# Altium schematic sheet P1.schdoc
size 1117 x 863 mm; Symbol: Drawing-Symbol_A4; @Project Name: WYVERN-E; @Page Count: 1; @Update Date: 2026-08-05; @Create Date: 2026-08-05; @Schematic Name: Schematic1; @Page No: 1; @Page Name: P1; Company: EasyEDA.com; Version: V1.0; Page Size: A4; Device: Drawing-Symbol_A4; @Create Time: 14:42:15; @Update Time: 14:42:15; Border: 1; Width: 4400; Height: 3400; Region Start: 1; X Region Count: 6; Y Region Count: 4; Blade Width: 10; Title Block Position: 3; @Board Name: Board1
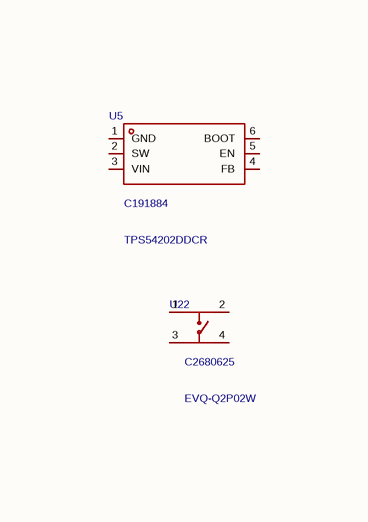
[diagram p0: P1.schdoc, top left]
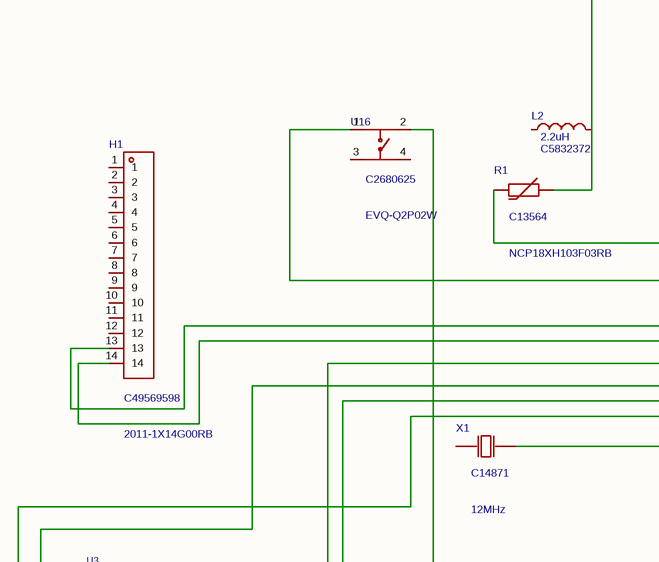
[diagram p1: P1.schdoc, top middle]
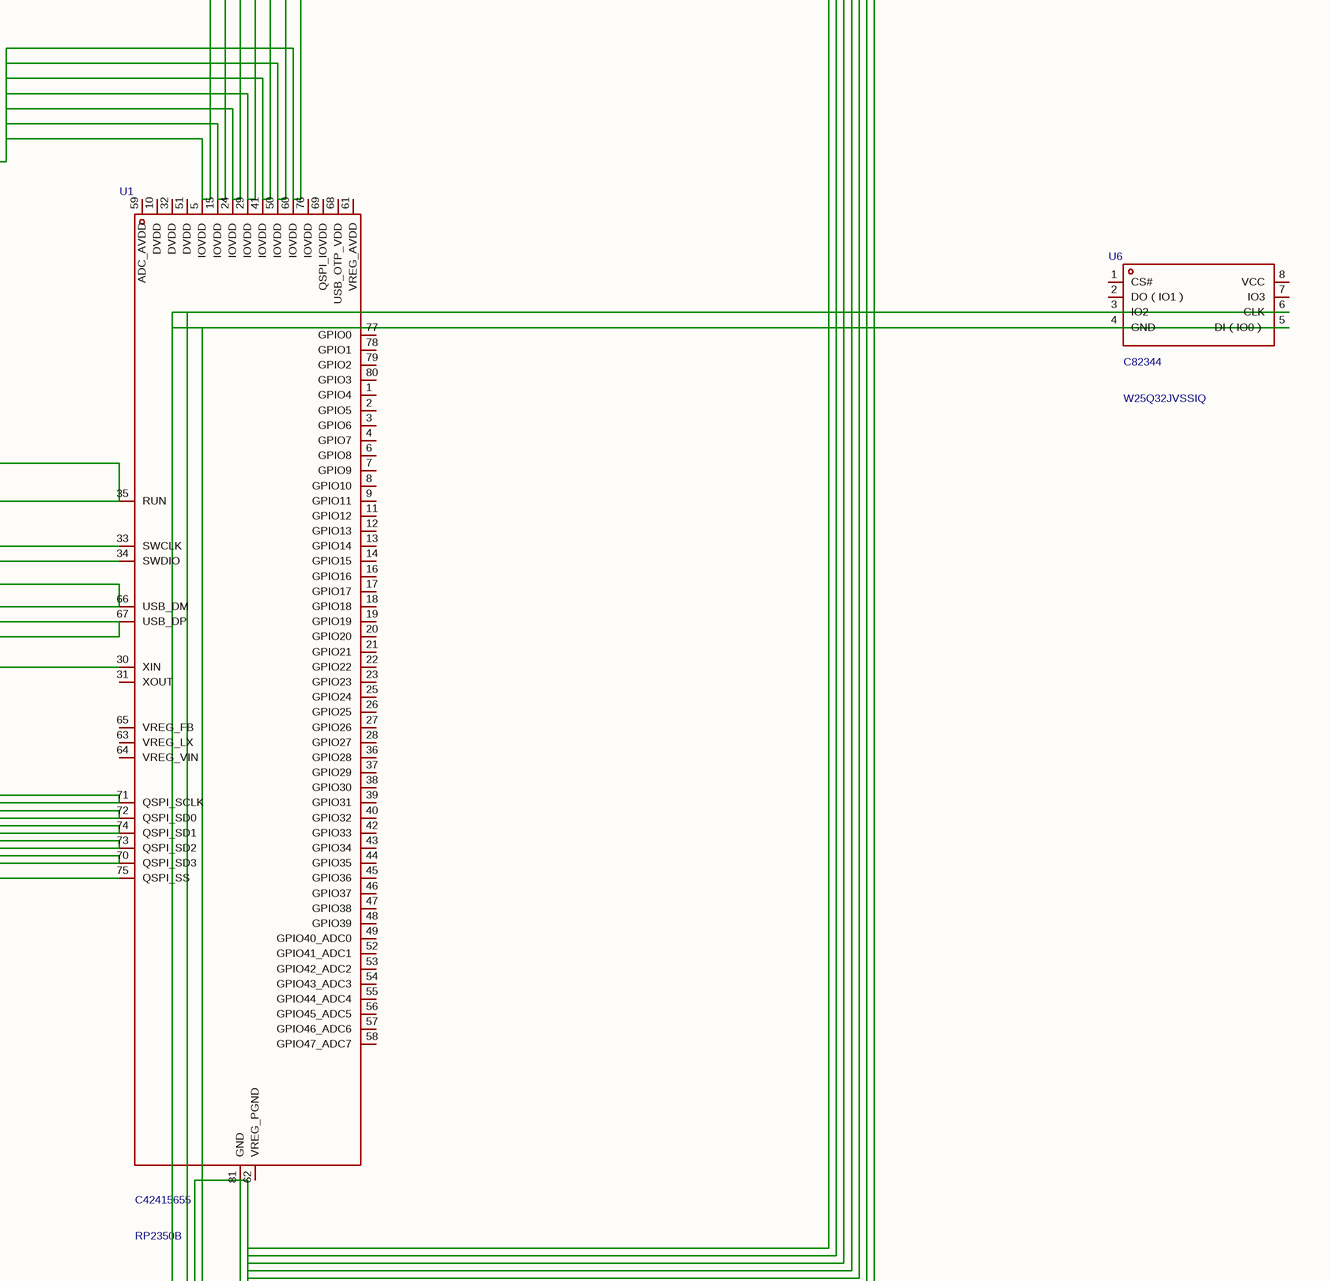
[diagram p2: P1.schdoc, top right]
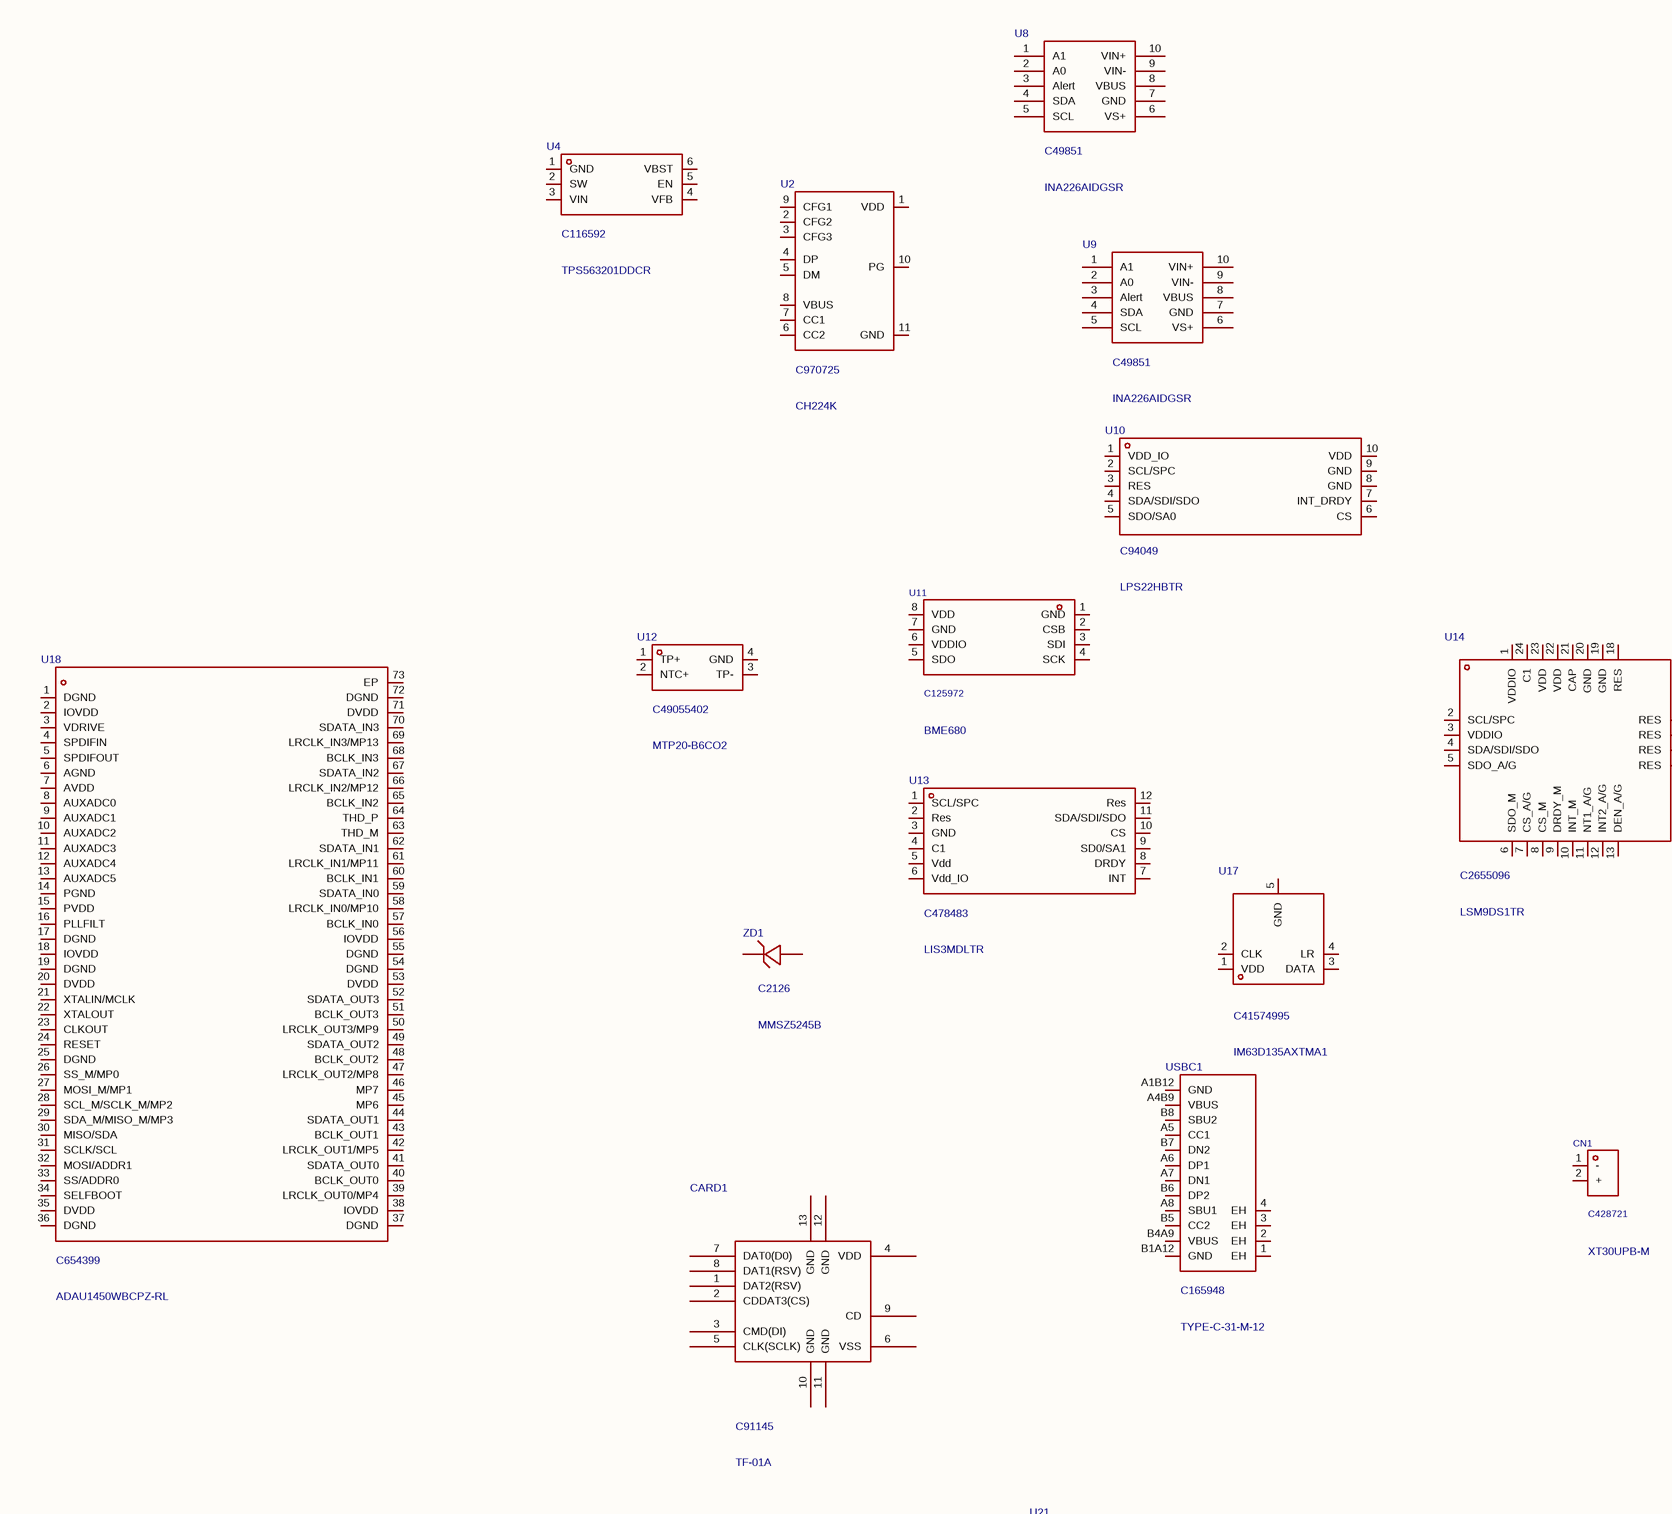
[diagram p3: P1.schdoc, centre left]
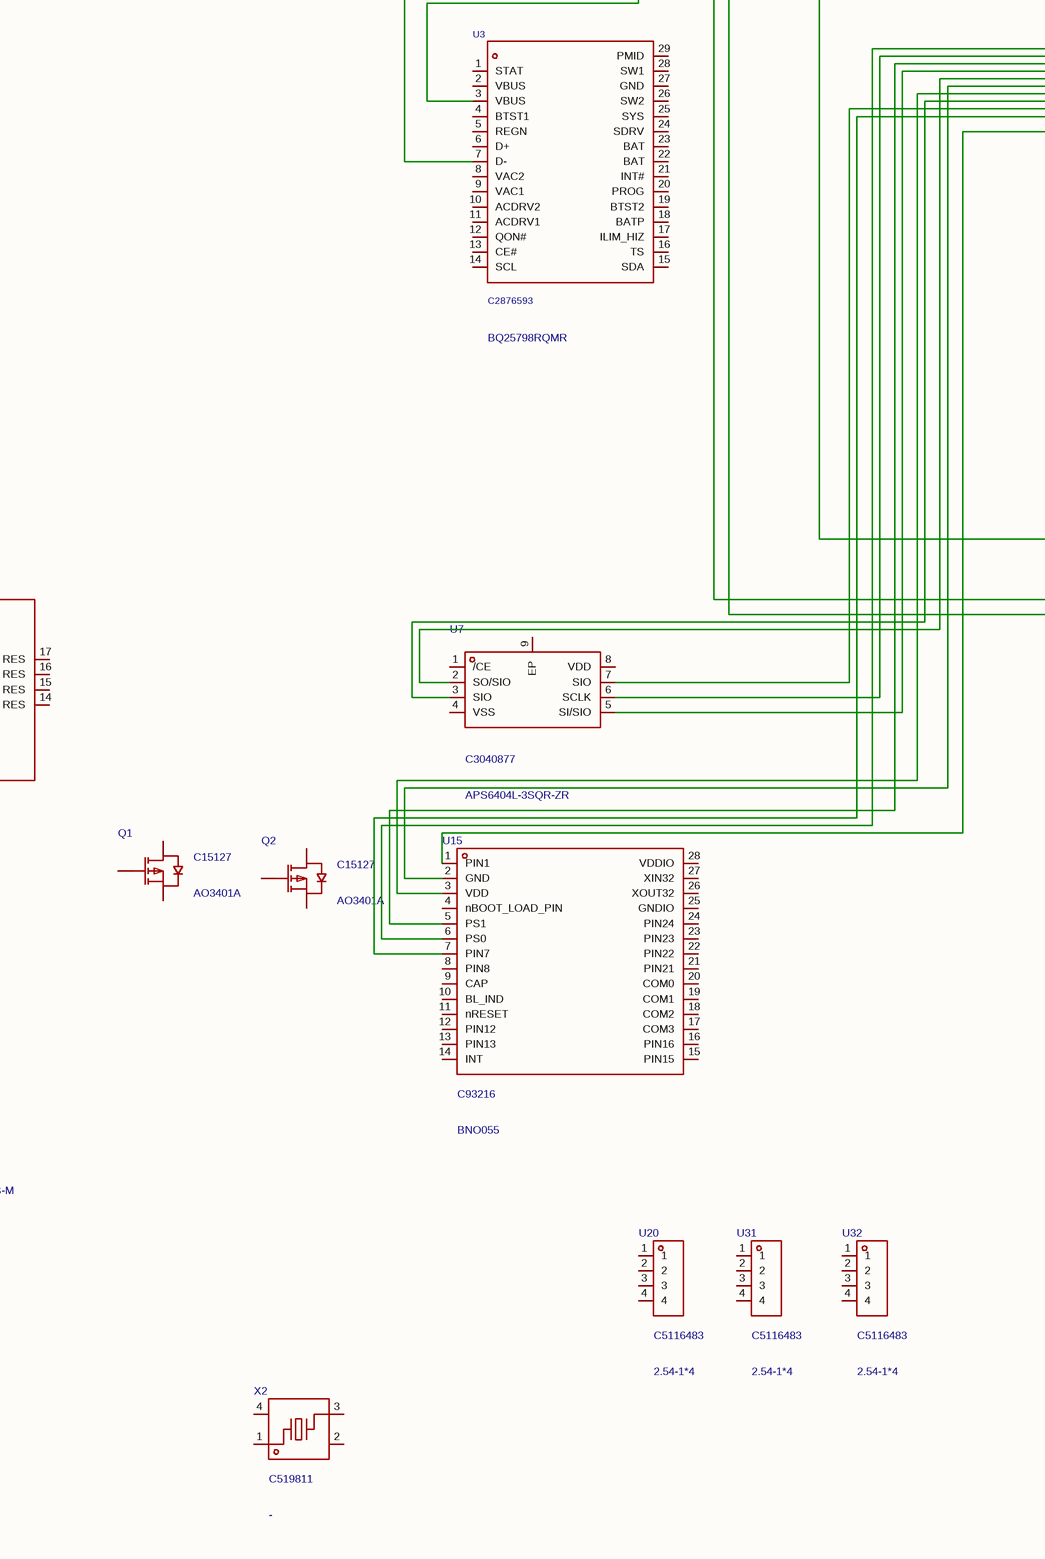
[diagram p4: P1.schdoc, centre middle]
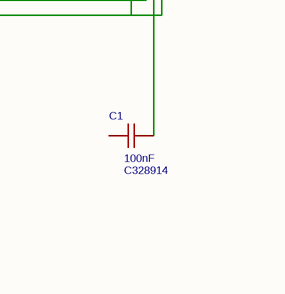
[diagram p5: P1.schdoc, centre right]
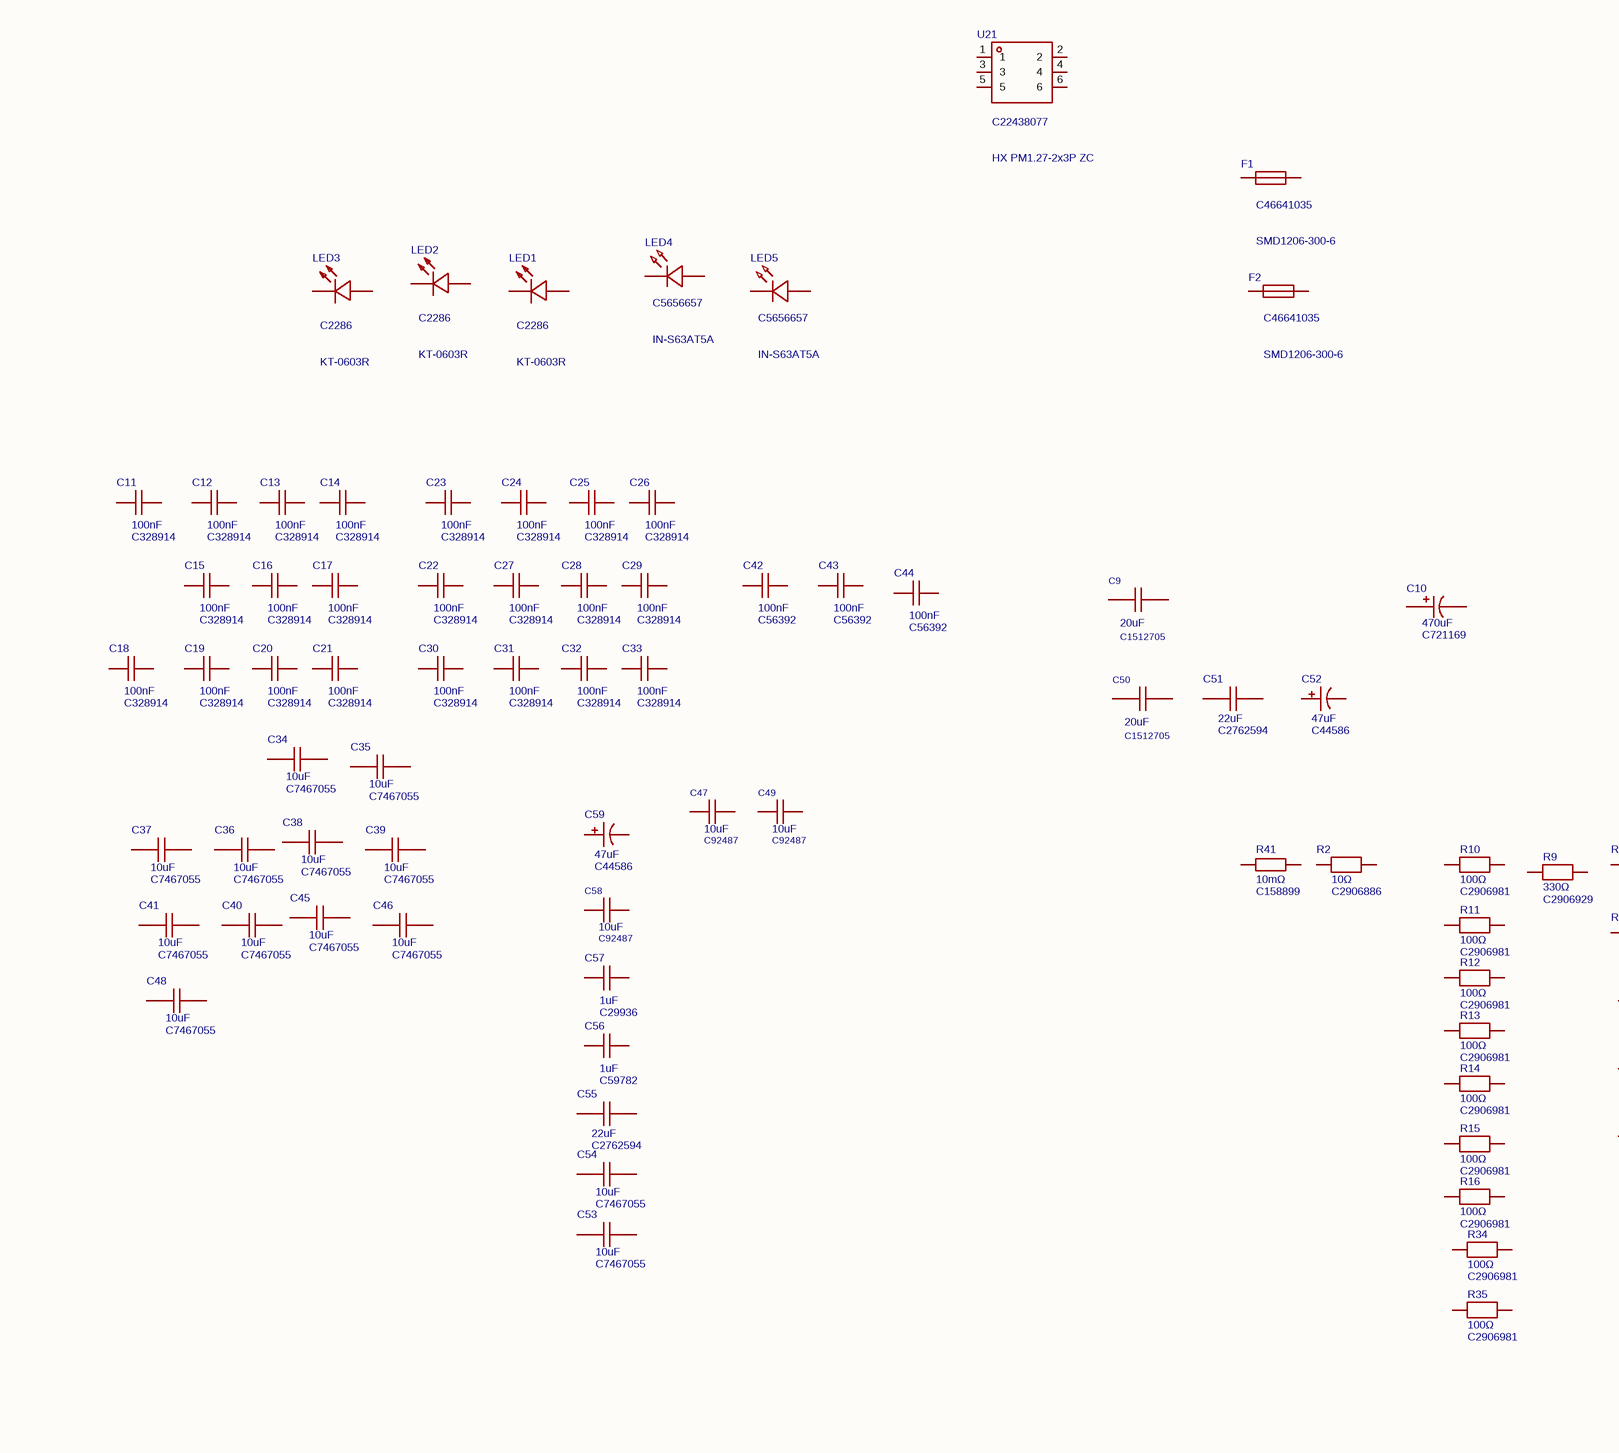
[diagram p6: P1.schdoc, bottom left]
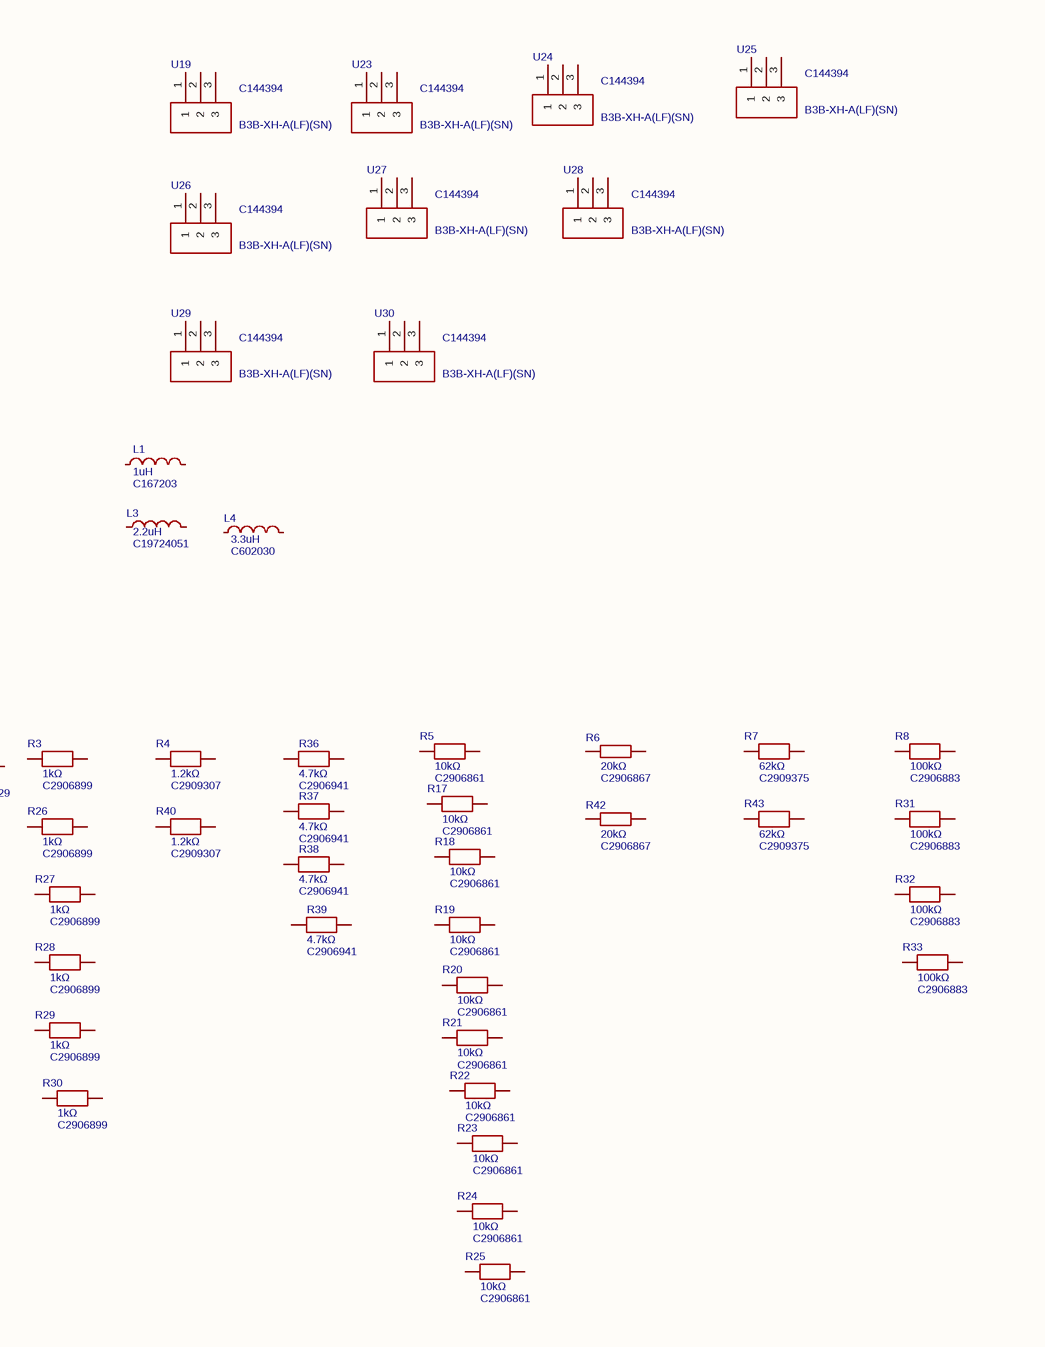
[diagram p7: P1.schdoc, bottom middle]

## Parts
C1  100nF  Supplier Part: C328914  [C0402]
C9  20uF  Supplier Part: C1512705  [C1812]
C10  470uF  Supplier Part: C721169  [CAP-TH_BD8.0-P3.50-D0.6-FD]
C11  100nF  Supplier Part: C328914  [C0402]
C12  100nF  Supplier Part: C328914  [C0402]
C13  100nF  Supplier Part: C328914  [C0402]
C14  100nF  Supplier Part: C328914  [C0402]
C15  100nF  Supplier Part: C328914  [C0402]
C16  100nF  Supplier Part: C328914  [C0402]
C17  100nF  Supplier Part: C328914  [C0402]
C18  100nF  Supplier Part: C328914  [C0402]
C19  100nF  Supplier Part: C328914  [C0402]
C20  100nF  Supplier Part: C328914  [C0402]
C21  100nF  Supplier Part: C328914  [C0402]
C22  100nF  Supplier Part: C328914  [C0402]
C23  100nF  Supplier Part: C328914  [C0402]
C24  100nF  Supplier Part: C328914  [C0402]
C25  100nF  Supplier Part: C328914  [C0402]
C26  100nF  Supplier Part: C328914  [C0402]
C27  100nF  Supplier Part: C328914  [C0402]
C28  100nF  Supplier Part: C328914  [C0402]
C29  100nF  Supplier Part: C328914  [C0402]
C30  100nF  Supplier Part: C328914  [C0402]
C31  100nF  Supplier Part: C328914  [C0402]
C32  100nF  Supplier Part: C328914  [C0402]
C33  100nF  Supplier Part: C328914  [C0402]
C34  10uF  Supplier Part: C7467055  [C0603]
C35  10uF  Supplier Part: C7467055  [C0603]
C36  10uF  Supplier Part: C7467055  [C0603]
C37  10uF  Supplier Part: C7467055  [C0603]
C38  10uF  Supplier Part: C7467055  [C0603]
C39  10uF  Supplier Part: C7467055  [C0603]
C40  10uF  Supplier Part: C7467055  [C0603]
C41  10uF  Supplier Part: C7467055  [C0603]
C42  100nF  Supplier Part: C56392  [C0402]
C43  100nF  Supplier Part: C56392  [C0402]
C44  100nF  Supplier Part: C56392  [C0402]
C45  10uF  Supplier Part: C7467055  [C0603]
C46  10uF  Supplier Part: C7467055  [C0603]
C47  10uF  Supplier Part: C92487  [C0603]
C48  10uF  Supplier Part: C7467055  [C0603]
C49  10uF  Supplier Part: C92487  [C0603]
C50  20uF  Supplier Part: C1512705  [C1812]
C51  22uF  Supplier Part: C2762594  [C0603]
C52  47uF  Supplier Part: C44586  [CAP-TH_BD5.0-P2.00-D0.8-FD]
C53  10uF  Supplier Part: C7467055  [C0603]
C54  10uF  Supplier Part: C7467055  [C0603]
C55  22uF  Supplier Part: C2762594  [C0603]
C56  1uF  Supplier Part: C59782  [C0603]
C57  1uF  Supplier Part: C29936  [C0603]
C58  10uF  Supplier Part: C92487  [C0603]
C59  47uF  Supplier Part: C44586  [CAP-TH_BD5.0-P2.00-D0.8-FD]
CARD1  TF-01A  Supplier Part: C91145  [TF-SMD_TF-01A]
CN1  XT30UPB-M  Supplier Part: C428721  [CONN-TH_XT30UPB-M]
F1  SMD1206-300-6  Supplier Part: C46641035  [F1206]
F2  SMD1206-300-6  Supplier Part: C46641035  [F1206]
H1  2011-1X14G00RB  Supplier Part: C49569598  [HDR-TH_14P-P2.54-H-M-W6.0-N]
L1  1uH  Supplier Part: C167203  [IND-SMD_L4.4-W4.2]
L2  2.2uH  Supplier Part: C5832372  [IND-SMD_L2.5-W2.0_MHCHL2520]
L3  2.2uH  Supplier Part: C19724051  [IND-SMD_L5.5-W5.2_NBMC0530N]
L4  3.3uH  Supplier Part: C602030  [IND-SMD_L4.0-W4.0]
LED1  KT-0603R  Supplier Part: C2286  [LED-SMD_L1.6-W0.8-R-RD]
LED2  KT-0603R  Supplier Part: C2286  [LED-SMD_L1.6-W0.8-R-RD]
LED3  KT-0603R  Supplier Part: C2286  [LED-SMD_L1.6-W0.8-R-RD]
LED4  IN-S63AT5A  Supplier Part: C5656657  [LED0603-RD]
LED5  IN-S63AT5A  Supplier Part: C5656657  [LED0603-RD]
Q1  AO3401A  Supplier Part: C15127  [SOT-23_L2.9-W1.3-P1.90-LS2.4-BR]
Q2  AO3401A  Supplier Part: C15127  [SOT-23_L2.9-W1.3-P1.90-LS2.4-BR]
R1  NCP18XH103F03RB  Supplier Part: C13564  [R0603]
R2  10Ω  Supplier Part: C2906886  [R0402]
R3  1kΩ  Supplier Part: C2906899  [R0402]
R4  1.2kΩ  Supplier Part: C2909307  [R0402]
R5  10kΩ  Supplier Part: C2906861  [R0402]
R6  20kΩ  Supplier Part: C2906867  [R0402]
R7  62kΩ  Supplier Part: C2909375  [R0402]
R8  100kΩ  Supplier Part: C2906883  [R0402]
R9  330Ω  Supplier Part: C2906929  [R0402]
R10  100Ω  Supplier Part: C2906981  [R0603]
R11  100Ω  Supplier Part: C2906981  [R0603]
R12  100Ω  Supplier Part: C2906981  [R0603]
R13  100Ω  Supplier Part: C2906981  [R0603]
R14  100Ω  Supplier Part: C2906981  [R0603]
R15  100Ω  Supplier Part: C2906981  [R0603]
R16  100Ω  Supplier Part: C2906981  [R0603]
R17  10kΩ  Supplier Part: C2906861  [R0402]
R18  10kΩ  Supplier Part: C2906861  [R0402]
R19  10kΩ  Supplier Part: C2906861  [R0402]
R20  10kΩ  Supplier Part: C2906861  [R0402]
R21  10kΩ  Supplier Part: C2906861  [R0402]
R22  10kΩ  Supplier Part: C2906861  [R0402]
R23  10kΩ  Supplier Part: C2906861  [R0402]
R24  10kΩ  Supplier Part: C2906861  [R0402]
R25  10kΩ  Supplier Part: C2906861  [R0402]
R26  1kΩ  Supplier Part: C2906899  [R0402]
R27  1kΩ  Supplier Part: C2906899  [R0402]
R28  1kΩ  Supplier Part: C2906899  [R0402]
R29  1kΩ  Supplier Part: C2906899  [R0402]
R30  1kΩ  Supplier Part: C2906899  [R0402]
R31  100kΩ  Supplier Part: C2906883  [R0402]
R32  100kΩ  Supplier Part: C2906883  [R0402]
R33  100kΩ  Supplier Part: C2906883  [R0402]
R34  100Ω  Supplier Part: C2906981  [R0603]
R35  100Ω  Supplier Part: C2906981  [R0603]
R36  4.7kΩ  Supplier Part: C2906941  [R0402]
R37  4.7kΩ  Supplier Part: C2906941  [R0402]
R38  4.7kΩ  Supplier Part: C2906941  [R0402]
R39  4.7kΩ  Supplier Part: C2906941  [R0402]
R40  1.2kΩ  Supplier Part: C2909307  [R0402]
R41  10mΩ  Supplier Part: C158899  [R0603]
R42  20kΩ  Supplier Part: C2906867  [R0402]
R43  62kΩ  Supplier Part: C2909375  [R0402]
U1  RP2350B  Supplier Part: C42415655  [QFN-80_L10.0-W10.0-P0.40-TL-EP3.4]
U2  CH224K  Supplier Part: C970725  [ESSOP-10_L4.9-W3.9-P1.0-LS6.0-TL-EP]
U3  BQ25798RQMR  Supplier Part: C2876593  [QFN-29_L4.0-W4.0-P0.40-TL-BQ25792RQMR]
U4  TPS563201DDCR  Supplier Part: C116592  [SOT-23-6_L2.9-W1.6-P0.95-LS2.8-BR]
U5  TPS54202DDCR  Supplier Part: C191884  [SOT-23-6_L2.9-W1.6-P0.95-LS2.8-BL]
U6  W25Q32JVSSIQ  Supplier Part: C82344  [SOIC-8_L5.3-W5.3-P1.27-LS8.0-BL]
U7  APS6404L-3SQR-ZR  Supplier Part: C3040877  [USON-8_L3.0-W2.0-P0.50-BL-EP]
U8  INA226AIDGSR  Supplier Part: C49851  [MSOP-10_L3.0-W3.0-P0.50-LS5.0-BL]
U9  INA226AIDGSR  Supplier Part: C49851  [MSOP-10_L3.0-W3.0-P0.50-LS5.0-BL]
U10  LPS22HBTR  Supplier Part: C94049  [HLGA-10L_LPS22HBTR]
U11  BME680  Supplier Part: C125972  [LGA-8_L3.0-W3.0-P0.80-TR]
U12  MTP20-B6CO2  Supplier Part: C49055402  [TO-46-4_BD5.5-P1.80_MTP20-B6CO2]
U13  LIS3MDLTR  Supplier Part: C478483  [LGA-12_L2.0-W2.0-P0.50-BL]
U14  LSM9DS1TR  Supplier Part: C2655096  [LGA-24_L3.5-W3.0-P0.43-TL]
U15  BNO055  Supplier Part: C93216  [LGA-28_L5.2-W3.8-P0.50-BL]
U16  EVQ-Q2P02W  Supplier Part: C2680625  [SW-SMD_4P-L6.5-W6.0-P4.00-LS6.6-TL]
U17  IM63D135AXTMA1  Supplier Part: C41574995  [MIC-SMD_5P-L3.5-W2.7_IM66D130AXTMA1]
U18  ADAU1450WBCPZ-RL  Supplier Part: C654399  [LFCSP-72_L10.0-W9.8-P0.50-LS10.2-TL-EP5.5]
U19  B3B-XH-A(LF)(SN)  Supplier Part: C144394  [CONN-TH_3P-P2.50_A2501WV2-3P]
U20  2.54-1*4  Supplier Part: C5116483  [HDR-TH_4P-P2.54-V-M-1]
U21  HX PM1.27-2x3P ZC  Supplier Part: C22438077  [HDR-TH_6P-HX-PM1.27-2X3P-ZC]
U22  EVQ-Q2P02W  Supplier Part: C2680625  [SW-SMD_4P-L6.5-W6.0-P4.00-LS6.6-TL]
U23  B3B-XH-A(LF)(SN)  Supplier Part: C144394  [CONN-TH_3P-P2.50_A2501WV2-3P]
U24  B3B-XH-A(LF)(SN)  Supplier Part: C144394  [CONN-TH_3P-P2.50_A2501WV2-3P]
U25  B3B-XH-A(LF)(SN)  Supplier Part: C144394  [CONN-TH_3P-P2.50_A2501WV2-3P]
U26  B3B-XH-A(LF)(SN)  Supplier Part: C144394  [CONN-TH_3P-P2.50_A2501WV2-3P]
U27  B3B-XH-A(LF)(SN)  Supplier Part: C144394  [CONN-TH_3P-P2.50_A2501WV2-3P]
U28  B3B-XH-A(LF)(SN)  Supplier Part: C144394  [CONN-TH_3P-P2.50_A2501WV2-3P]
U29  B3B-XH-A(LF)(SN)  Supplier Part: C144394  [CONN-TH_3P-P2.50_A2501WV2-3P]
U30  B3B-XH-A(LF)(SN)  Supplier Part: C144394  [CONN-TH_3P-P2.50_A2501WV2-3P]
U31  2.54-1*4  Supplier Part: C5116483  [HDR-TH_4P-P2.54-V-M-1]
U32  2.54-1*4  Supplier Part: C5116483  [HDR-TH_4P-P2.54-V-M-1]
USBC1  TYPE-C-31-M-12  Supplier Part: C165948  [USB-C_SMD-TYPE-C-31-M-12_1]
X1  12MHz  Supplier Part: C14871  [HC-49S_L11.4-W4.8]
X2  -  Supplier Part: C519811  [CRYSTAL-SMD_4P-L3.2-W2.5-BL]
ZD1  MMSZ5245B  Supplier Part: C2126  [SOD-123_L2.8-W1.8-LS3.7-RD]

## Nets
NetC1_2: C1.2 U1.81(GND) U16.2
NetH1_13: H1.13 U1.33(SWCLK)
NetH1_14: H1.14 U1.34(SWDIO)
NetL2_2: L2.2 R1.2 U1.5(IOVDD) U1.15(IOVDD) U1.24(IOVDD) U1.29(IOVDD) U1.41(IOVDD) U1.50(IOVDD) U1.60(IOVDD)
NetR1_1: R1.1 U1.35(RUN) U16.1
NetU1_30: U1.30(XIN) X1.1(OSC1)
NetU1_66: U1.66(USB_DM) U1.67(USB_DP) U3.3(VBUS) U3.7(D-) U6.3(IO2) U6.4(GND) U6.5(DI（IO0）) U6.6(CLK)
NetU1_70: U1.70(QSPI_SD3) U7.7(SIO) U15.7(PIN7)
NetU1_71: U1.71(QSPI_SCLK) U7.6(SCLK) U15.6(PS0)
NetU1_72: U1.72(QSPI_SD0) U7.5(SI/SIO) U15.5(PS1)
NetU1_73: U1.73(QSPI_SD2) U7.3(SIO) U15.3(VDD)
NetU1_74: U1.74(QSPI_SD1) U7.2(SO/SIO) U15.2(GND)
NetU1_75: U1.75(QSPI_SS) U15.1(PIN1)

Not connected (* = marked no-connect by the designer): C1 1; C9 1 2; C10 1 2; C11 1 2; C12 1 2; C13 1 2; C14 1 2; C15 1 2; C16 1 2; C17 1 2; C18 1 2; C19 1 2; C20 1 2; C21 1 2; C22 1 2; C23 1 2; C24 1 2; C25 1 2; C26 1 2; C27 1 2; C28 1 2; C29 1 2; C30 1 2; C31 1 2; C32 1 2; C33 1 2; C34 1 2; C35 1 2; C36 1 2; C37 1 2; C38 1 2; C39 1 2; C40 1 2; C41 1 2; C42 1 2; C43 1 2; C44 1 2; C45 1 2; C46 1 2; C47 1 2; C48 1 2; C49 1 2; C50 1 2; C51 1 2; C52 1 2; C53 1 2; C54 1 2; C55 1 2; C56 1 2; C57 1 2; C58 1 2; C59 1 2; CARD1 1(DAT2(RSV)) 2(CDDAT3(CS)) 3(CMD(DI)) 4(VDD) 5(CLK(SCLK)) 6(VSS) 7(DAT0(D0)) 8(DAT1(RSV)) 9(CD) 10(GND) 11(GND) 12(GND) 13(GND); CN1 1(-) 2(+); F1 1 2; F2 1 2; H1 1 2 3 4 5 6 7 8 9 10 11 12; L1 1 2; L2 1; L3 1 2; L4 1 2; LED1 1(A) 2(K); LED2 1(A) 2(K); LED3 1(A) 2(K); LED4 1(C) 2(A); LED5 1(C) 2(A); Q1 1(G) 2(S) 3(D); Q2 1(G) 2(S) 3(D); R2 1 2; R3 1 2; R4 1 2; R5 1 2; R6 1 2; R7 1 2; R8 1 2; R9 1 2; R10 1 2; R11 1 2; R12 1 2; R13 1 2; R14 1 2; R15 1 2; R16 1 2; R17 1 2; R18 1 2; R19 1 2; R20 1 2; R21 1 2; R22 1 2; R23 1 2; R24 1 2; R25 1 2; R26 1 2; R27 1 2; R28 1 2; R29 1 2; R30 1 2; R31 1 2; R32 1 2; R33 1 2; R34 1 2; R35 1 2; R36 1 2; R37 1 2; R38 1 2; R39 1 2; R40 1 2; R41 1 2; R42 1 2; R43 1 2; U1 1(GPIO4) 2(GPIO5) 3(GPIO6) 4(GPIO7) 6(GPIO8) 7(GPIO9) 8(GPIO10) 9(GPIO11) 10(DVDD) 11(GPIO12) 12(GPIO13) 13(GPIO14) 14(GPIO15) 16(GPIO16) 17(GPIO17) 18(GPIO18) 19(GPIO19) 20(GPIO20) 21(GPIO21) 22(GPIO22) 23(GPIO23) 25(GPIO24) 26(GPIO25) 27(GPIO26) 28(GPIO27) 31(XOUT) 32(DVDD) 36(GPIO28) 37(GPIO29) 38(GPIO30) 39(GPIO31) 40(GPIO32) 42(GPIO33) 43(GPIO34) 44(GPIO35) 45(GPIO36) 46(GPIO37) 47(GPIO38) 48(GPIO39) 49(GPIO40_ADC0) 51(DVDD) 52(GPIO41_ADC1) 53(GPIO42_ADC2) 54(GPIO43_ADC3) 55(GPIO44_ADC4) 56(GPIO45_ADC5) 57(GPIO46_ADC6) 58(GPIO47_ADC7) 59(ADC_AVDD) 61(VREG_AVDD) 62(VREG_PGND) 63(VREG_LX) 64(VREG_VIN) 65(VREG_FB) 68(USB_OTP_VDD) 69(QSPI_IOVDD) 76(IOVDD) 77(GPIO0) 78(GPIO1) 79(GPIO2) 80(GPIO3); U2 1(VDD) 2(CFG2) 3(CFG3) 4(DP) 5(DM) 6(CC2) 7(CC1) 8(VBUS) 9(CFG1) 10(PG) 11(GND); U3 1(STAT) 2(VBUS) 4(BTST1) 5(REGN) 6(D+) 8(VAC2) 9(VAC1) 10(ACDRV2) 11(ACDRV1) 12(QON#) 13(CE#) 14(SCL) 15(SDA) 16(TS) 17(ILIM_HIZ) 18(BATP) 19(BTST2) 20(PROG) 21(INT#) 22(BAT) 23(BAT) 24(SDRV) 25(SYS) 26(SW2) 27(GND) 28(SW1) 29(PMID); U4 1(GND) 2(SW) 3(VIN) 4(VFB) 5(EN) 6(VBST); U5 1(GND) 2(SW) 3(VIN) 4(FB) 5(EN) 6(BOOT); U6 1(CS#) 2(DO（IO1）) 7(IO3) 8(VCC); U7 1(/CE) 4(VSS) 8(VDD) 9(EP); U8 1(A1) 2(A0) 3(Alert) 4(SDA) 5(SCL) 6(VS+) 7(GND) 8(VBUS) 9(VIN-) 10(VIN+); U9 1(A1) 2(A0) 3(Alert) 4(SDA) 5(SCL) 6(VS+) 7(GND) 8(VBUS) 9(VIN-) 10(VIN+); U10 1(VDD_IO) 2(SCL/SPC) 3(RES) 4(SDA/SDI/SDO) 5(SDO/SA0) 6(CS) 7(INT_DRDY) 8(GND) 9(GND) 10(VDD); U11 1(GND) 2(CSB) 3(SDI) 4(SCK) 5(SDO) 6(VDDIO) 7(GND) 8(VDD); U12 1(TP+) 2(NTC+) 3(TP-) 4(GND); U13 1(SCL/SPC) 2(Res) 3(GND) 4(C1) 5(Vdd) 6(Vdd_IO) 7(INT) 8(DRDY) 9(SD0/SA1) 10(CS) 11(SDA/SDI/SDO) 12(Res); U14 1(VDDIO) 2(SCL/SPC) 3(VDDIO) 4(SDA/SDI/SDO) 5(SDO_A/G) 6(SDO_M) 7(CS_A/G) 8(CS_M) 9(DRDY_M) 10(INT_M) 11(NT1_A/G) 12(INT2_A/G) 13(DEN_A/G) 14(RES) 15(RES) 16(RES) 17(RES) 18(RES) 19(GND) 20(GND) 21(CAP) 22(VDD) 23(VDD) 24(C1); U15 4(nBOOT_LOAD_PIN) 8(PIN8) 9(CAP) 10(BL_IND) 11(nRESET) 12(PIN12) 13(PIN13) 14(INT) 15(PIN15) 16(PIN16) 17(COM3) 18(COM2) 19(COM1) 20(COM0) 21(PIN21) 22(PIN22) 23(PIN23) 24(PIN24) 25(GNDIO) 26(XOUT32) 27(XIN32) 28(VDDIO); U16 3 4; U17 1(VDD) 2(CLK) 3(DATA) 4(LR) 5(GND); U18 1(DGND) 2(IOVDD) 3(VDRIVE) 4(SPDIFIN) 5(SPDIFOUT) 6(AGND) 7(AVDD) 8(AUXADC0) 9(AUXADC1) 10(AUXADC2) 11(AUXADC3) 12(AUXADC4) 13(AUXADC5) 14(PGND) 15(PVDD) 16(PLLFILT) 17(DGND) 18(IOVDD) 19(DGND) 20(DVDD) 21(XTALIN/MCLK) 22(XTALOUT) 23(CLKOUT) 24(RESET) 25(DGND) 26(SS_M/MP0) 27(MOSI_M/MP1) 28(SCL_M/SCLK_M/MP2) 29(SDA_M/MISO_M/MP3) 30(MISO/SDA) 31(SCLK/SCL) 32(MOSI/ADDR1) 33(SS/ADDR0) 34(SELFBOOT) 35(DVDD) 36(DGND) 37(DGND) 38(IOVDD) 39(LRCLK_OUT0/MP4) 40(BCLK_OUT0) 41(SDATA_OUT0) 42(LRCLK_OUT1/MP5) 43(BCLK_OUT1) 44(SDATA_OUT1) 45(MP6) 46(MP7) 47(LRCLK_OUT2/MP8) 48(BCLK_OUT2) 49(SDATA_OUT2) 50(LRCLK_OUT3/MP9) 51(BCLK_OUT3) 52(SDATA_OUT3) 53(DVDD) 54(DGND) 55(DGND) 56(IOVDD) 57(BCLK_IN0) 58(LRCLK_IN0/MP10) 59(SDATA_IN0) 60(BCLK_IN1) 61(LRCLK_IN1/MP11) 62(SDATA_IN1) 63(THD_M) 64(THD_P) 65(BCLK_IN2) 66(LRCLK_IN2/MP12) 67(SDATA_IN2) 68(BCLK_IN3) 69(LRCLK_IN3/MP13) 70(SDATA_IN3) 71(DVDD) 72(DGND) 73(EP); U19 1 2 3; U20 1 2 3 4; U21 1 2 3 4 5 6; U22 1 2 3 4; U23 1 2 3; U24 1 2 3; U25 1 2 3; U26 1 2 3; U27 1 2 3; U28 1 2 3; U29 1 2 3; U30 1 2 3; U31 1 2 3 4; U32 1 2 3 4; USBC1 1(EH) 2(EH) 3(EH) 4(EH) A1B12(GND) A4B9(VBUS) A5(CC1) A6(DP1) A7(DN1) A8(SBU1) B1A12(GND) B4A9(VBUS) B5(CC2) B6(DP2) B7(DN2) B8(SBU2); X1 2(OSC2); X2 1 2(GND) 3 4(GND); ZD1 1(K) 2(A)

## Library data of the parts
C1 C11-C33 = FN15X104K160PNG: Capacitance:100nF Tolerance:±10% Tolerance:±10% Voltage Rating:16V Temperature Coefficient:X7R; Manufacturer: PSA(信昌电陶); AddInBom: yes; ModelId: b7d13df3e9464d7a99d0651d1a5b4d570819f05c4eef4c71ace90d822a990e87; ModelName: C0402_L1.0-W0.5-H0.5; ModelTransform: 39.37,19.685,0,0,0,0,0,0,0; Tolerance: ±10%; Voltage Rating: 16V; Temperature Coefficient: X7R
C9 C50 = C1812C206K3RLCAUTO: Capacitance:20uF Tolerance:±10% Tolerance:±10% Voltage Rated: Temperature Coefficient:; Manufacturer: KEMET(基美); AddInBom: yes; ModelId: 9490267e11c744c49bc8222b92720aba0819f05c4eef4c71ace90d822a990e87; ModelName: C1812_L4.5-W3.2-H2.6; ModelTransform: 177.165,125.984,0,0,0,0,0.0005,0,0; Tolerance: ±10%
C10 = ERF1EM471F12OT: Capacitance:470uF Tolerance:±20% Tolerance:±20% Voltage Rating:25V Ripple Current:- Equivalent Series Resistance(ESR):- Pin Spacing:3.5mm Diameter:8mm Height - Seated (Max):12mm Lifetime:- Operating Temperature:-40℃~+105℃ Operating Temperature:-40℃~+105℃; Manufacturer: AISHI(艾华集团); AddInBom: yes; ModelId: 26f37486632942dc87f6308ee91e8f400819f05c4eef4c71ace90d822a990e87; ModelName: CAP-TH_D8.0-H8.0-P3.50; ModelTransform: 314.96,314.862,0,180,0,0,0,0,-137.795; Tolerance: ±20%; Voltage Rating: 25V; Pin Spacing: 3.5mm
C34-C41 C45 C46 C48 C53 C54 = FCC0603X106M250CT: Capacitance:10uF Tolerance:±20% Tolerance:±20% Voltage Rating:25V Temperature Coefficient:X5R; Manufacturer: FOJAN(富捷); AddInBom: yes; ModelId: 624118aa3cc7497086c383c2d72e08520819f05c4eef4c71ace90d822a990e87; ModelName: C0603_L1.6-W0.8-H0.8; ModelTransform: 62.992,31.496,0,0,0,0,0,0,0; Tolerance: ±20%; Voltage Rating: 25V; Temperature Coefficient: X5R
C42-C44 = 0402B104K250NT: Capacitance:100nF Tolerance:±10% Tolerance:±10% Voltage Rating:25V Temperature Coefficient:X7R; Manufacturer: FH(风华); AddInBom: yes; ModelId: b7d13df3e9464d7a99d0651d1a5b4d570819f05c4eef4c71ace90d822a990e87; ModelName: C0402_L1.0-W0.5-H0.5; ModelTransform: 39.37,19.685,0,0,0,0,0,0,0; Tolerance: ±10%; Voltage Rating: 25V; Temperature Coefficient: X7R
C47 C49 C58 = CL10A106MO8NQNC: Capacitance:10uF Tolerance:±20% Tolerance:±20% Voltage Rating:16V Temperature Coefficient:X5R; Manufacturer: SAMSUNG(三星); AddInBom: yes; ModelId: 624118aa3cc7497086c383c2d72e08520819f05c4eef4c71ace90d822a990e87; ModelName: C0603_L1.6-W0.8-H0.8; ModelTransform: 62.992,31.496,0,0,0,0,0,0,0; Tolerance: ±20%; Voltage Rating: 16V; Temperature Coefficient: X5R
C51 C55 = CL10A226MO7JZNC: Capacitance:22uF Tolerance:±20% Tolerance:±20% Voltage Rating:16V Temperature Coefficient:X5R; Manufacturer: SAMSUNG(三星); AddInBom: yes; ModelId: 624118aa3cc7497086c383c2d72e08520819f05c4eef4c71ace90d822a990e87; ModelName: C0603_L1.6-W0.8-H0.8; ModelTransform: 62.992,31.496,0,0,0,0,0,0,0; Tolerance: ±20%; Voltage Rating: 16V; Temperature Coefficient: X5R
C52 C59 = KS476M025D07RR0VH2FP0: Capacitance:47uF Tolerance:±20% Tolerance:±20% Voltage Rating:25V Pin Spacing:2mm Diameter:5mm Height - Seated (Max):7mm Lifetime:1000hrs@105℃ Operating Temperature:-40℃~+105℃ Operating Temperature:-40℃~+105℃; Manufacturer: Chengx(承兴); Symbol: 47uF 25V 5*7; AddInBom: yes; ModelId: a6753ac7f17a4fce96dd233a0f76b1540819f05c4eef4c71ace90d822a990e87; ModelName: CAP-TH_D5.0×H7.0×P2.0; ModelTransform: 197.091,196.7911,0,0,0,0,0,0,-137.795; Tolerance: ±20%; Voltage Rating: 25V; Pin Spacing: 2mm
C56 = CL10B105KO8NNNC: Capacitance:1uF Tolerance:±10% Tolerance:±10% Voltage Rating:16V Temperature Coefficient:X7R; Manufacturer: SAMSUNG(三星); AddInBom: yes; ModelId: 624118aa3cc7497086c383c2d72e08520819f05c4eef4c71ace90d822a990e87; ModelName: C0603_L1.6-W0.8-H0.8; ModelTransform: 62.992,31.496,0,0,0,0,0,0,0; Tolerance: ±10%; Voltage Rating: 16V; Temperature Coefficient: X7R
C57 = CL10B105KA8NNNC: Capacitance:1uF Tolerance:±10% Tolerance:±10% Voltage Rating:25V Temperature Coefficient:X7R; Manufacturer: SAMSUNG(三星); AddInBom: yes; ModelId: 624118aa3cc7497086c383c2d72e08520819f05c4eef4c71ace90d822a990e87; ModelName: C0603_L1.6-W0.8-H0.8; ModelTransform: 62.992,31.496,0,0,0,0,0,0,0; Tolerance: ±10%; Voltage Rating: 25V; Temperature Coefficient: X7R
CARD1 = TF-01A_C91145: Card Connection Mode:Push-Push Card Type:MicroSD Card (TF Card) Connector Type:Connector and Ejector Additional Card Detection Pins:- Supplementary Features:With Locating Pins Height Above Board:1.85mm Operating Temperature:- Operating Temperature:-; Manufacturer: 韩国韩荣; Add into BOM: yes; ModelId: 5685a23adc9a4e3e9b914abe5ae03aae0819f05c4eef4c71ace90d822a990e87; ModelTransform: 633.85696,590.65303,0,0,0,0,0,-85.63,-23.622
CN1 = XT30UPB-M: Rated current:15A Rated voltage: colour:Yellow Connector type:Model aircraft plug contact resistance: interface form:Male insulating material: metal material:Gold plating; Manufacturer: AMASS(艾迈斯); Add into BOM: yes; ModelId: 8606296c6a2a4a0aa30f28b26a2c1e3a0819f05c4eef4c71ace90d822a990e87; ModelTransform: 401.574,204.724,0,0,0,0,0,0,-78.74; Rated current: 15A; interface form: Male
F1 F2 = SMD1206-300-6: Voltage - Max:6V Current - Max:40A Hold Current:3A Trip Current:6A Power Dissipation:1W Resistance - Initial (Ri) (Min):10mΩ Resistance - Post Trip (R1) (Max):50mΩ Time to Trip(Max):4s Operating Temperature:-40℃~+85℃ Operating Temperature:-40℃~+85℃ Length; Manufacturer: R+O(宏嘉诚); Add into BOM: yes; ModelId: 61372169742747e19cbd4ac5ee5e48b10819f05c4eef4c71ace90d822a990e87; ModelName: F1206_L3.2-W1.7-H0.6; ModelTransform: 125.984,66.929,0,0,0,0,0,0,0; Voltage - Max: 6V; Current - Max: 40A; Hold Current: 3A; Trip Current: 6A; Power Dissipation: 1W; Resistance - Initial (Ri) (Min): 10mΩ; Resistance - Post Trip (R1) (Max): 50mΩ; Time to Trip(Max): 4s
H1 = 2011-1X14G00RB: Pin Structure:1x14P Pitch:2.54mm Circluar Pins/Square Pins:Pin Header Mounting Type:Right Angle Number of Rows:1 Number of Pins:14P Current Rating:3A Voltage Rating (Max):600V Length of Mating Pin:6mm Insulation Height:2.5mm Length of End Connection Pin:3; Manufacturer: WingTAT(格林柏); Add into BOM: yes; ModelId: 486cde91a464408db3adaf1731e349420819f05c4eef4c71ace90d822a990e87; ModelTransform: 1399.997,336.22,0,0,0,0,0,-118.11,-118.11; Pin Structure: 1x14P; Pitch: 2.54mm; Current Rating: 3A; Voltage Rating (Max): 600V
L1 = FXL0420-1R0-M: Inductance:1uH Tolerance:±20% Tolerance:±20% Current Rating:6A Current - Saturation(Isat):7A DC Resistance(DCR):27mΩ Type:Molded Inductor; Manufacturer: cjiang(长江微电); AddInBom: yes; ModelId: 202f222253c645ab9b4a671ae12ae5590819f05c4eef4c71ace90d822a990e87; ModelName: IND-SMD_L4.2-W4.4-H2.0; ModelTransform: 173.228,165.354,0,0,0,0,0,0,0; Tolerance: ±20%; Current Rating: 6A; Current - Saturation(Isat): 7A; DC Resistance(DCR): 27mΩ
L2 = FTC252012S2R2MBCA: Inductance:2.2uH Tolerance:±20% Tolerance:±20% Current Rating:3A Current - Saturation(Isat):3.8A DC Resistance(DCR):55mΩ Type:-; Manufacturer: cjiang(长江微电); AddInBom: yes; ModelId: 6030ee72033e42b3943c7a42b03bf5750819f05c4eef4c71ace90d822a990e87; ModelTransform: 98.425,78.74,0,0,0,0,0,0,0; Tolerance: ±20%; Current Rating: 3A; Current - Saturation(Isat): 3.8A; DC Resistance(DCR): 55mΩ
L3 = CY0530AT125DS-2R2MCY: Inductance:2.2uH Tolerance:±20% Tolerance:±20% Current Rating:6A Current - Saturation(Isat):6.7A DC Resistance(DCR):17.3mΩ Type:- Ratings:-; Manufacturer: Sumida(胜美达); AddInBom: yes; Tolerance: ±20%; Current Rating: 6A; Current - Saturation(Isat): 6.7A; DC Resistance(DCR): 17.3mΩ
L4 = FHD4020S-3R3MT: Inductance:3.3uH Tolerance:±20% Tolerance:±20% Current Rating:4A Current - Saturation(Isat):5.9A DC Resistance(DCR):73mΩ Type:Winding Inductor; Manufacturer: cjiang(长江微电); AddInBom: yes; ModelId: eb765a5a931c40af9a8ef05b08821f350819f05c4eef4c71ace90d822a990e87; ModelName: IND-SMD_L4.0-W4.0-H1.9; ModelTransform: 157.48,157.484,0,0,0,0,0,0,0; Tolerance: ±20%; Current Rating: 4A; Current - Saturation(Isat): 5.9A; DC Resistance(DCR): 73mΩ
LED1-LED3 = KT-0603R: Lamp Holder Type:1.6mm x 0.8mm square LED Illumination Color:Red Voltage - Forward(Vf):1.8V~2.4V Voltage - Forward(Vf):1.8V~2.4V Power(Watts):40mW Forward Current:20mA Wavelength - Dominant:615nm~630nm Wavelength - Dominant:615nm~630nm Peak Wavelength:645; Manufacturer: KENTO; Add into BOM: yes; ModelId: 19cc79473bbc420a8203ad67d1a57d420819f05c4eef4c71ace90d822a990e87; ModelName: LED0603_L1.6-W0.8-H0.6; ModelTransform: 63.7794,31.496,0,0,0,0,0,0,0; Illumination Color: Red; Power(Watts): 40mW; Forward Current: 20mA; Peak Wavelength: 645nm; Diode Configuration: Discrete Diode; Lens Color: Water Clear; Luminous Intensity: 300mcd; Viewing Angle: 120°
LED4 LED5 = IN-S63AT5A: Lamp Holder Type:- Illumination Color:Amber Voltage - Forward(Vf):2V Voltage - Forward(Vf):2V Power(Watts):75mW Forward Current:5mA Wavelength - Dominant:605nm Wavelength - Dominant:605nm Peak Wavelength:609nm Diode Configuration:Discrete Diode Lens Color; Manufacturer: Inolux; Add into BOM: yes; ModelId: 5e3b568068dd46cf8019c1d1baa0031b0819f05c4eef4c71ace90d822a990e87; ModelTransform: 63.7794,32.283,0,0,0,0,0,0,0; Illumination Color: Amber; Voltage - Forward(Vf): 2V; Power(Watts): 75mW; Forward Current: 5mA; Wavelength - Dominant: 605nm; Peak Wavelength: 609nm; Lens Color: Water Clear; Luminous Intensity: 35mcd; Viewing Angle: 120°
Q1 Q2 = AO3401A_C15127: Number:1 P-Channel Drain to Source Voltage:30V Current - Continuous Drain(Id):4A RDS(on):47mΩ@10V；85mΩ@2.5V；60mΩ@4.5V Pd - Power Dissipation:- Gate Threshold Voltage (Vgs(th)):900mV Gate Charge(Qg):14nC@10V Input Capacitance(Ciss):645pF Reverse Transfer C; Manufacturer: AOS; Add into BOM: yes; ModelId: 62a57c6760504a01965db6419a6d07df0819f05c4eef4c71ace90d822a990e87; ModelName: SOT-23-3P_L2.9-W1.3-H1.0-LS2.4-P0.95; ModelTransform: 98.64468,114.173,0,180,0,0,0.001,-0.002,0; Drain to Source Voltage: 30V; Current - Continuous Drain(Id): 4A; Gate Threshold Voltage (Vgs(th)): 900mV; Input Capacitance(Ciss): 645pF; Reverse Transfer Capacitance (Crss@Vds): 55pF; Output Capacitance(Coss): 80pF
R1 = NCP18XH103F03RB: Power(Watts):100mW Resistance @ 25℃:10kΩ Resistance Tolerance:±1% Resistance Tolerance:±1% B Constant Tolerance:±1% B Constant (25℃/50℃):3380K B Constant (25℃/75℃):- B Constant (25℃/85℃):3434K B Constant (25℃/100℃):3455K Steady State Current (Max):310uA D; Manufacturer: muRata(村田); Add into BOM: yes; ModelId: 112863783b5b41f1b5254f87eedc79320819f05c4eef4c71ace90d822a990e87; ModelTransform: 31.8897,63.7794,0,90,0,0,0,0,0; Power(Watts): 100mW; Resistance @ 25℃: 10kΩ; Resistance Tolerance: ±1%; B Constant (25℃/50℃): 3380K; B Constant (25℃/85℃): 3434K; B Constant (25℃/100℃): 3455K; Steady State Current (Max): 310uA; Dissipation Factor: 1mW/℃
R2 = FRC0402J100 TS: Type:Thick Film Resistor Resistance:10Ω Tolerance:±5% Tolerance:±5% Power(Watts):62.5mW Voltage-Supply(Max):50V Temperature Coefficient:±200ppm/℃ Temperature Coefficient:±200ppm/℃ Operating Temperature:-55℃~+155℃ Operating Temperature:-55℃~+155℃; Manufacturer: FOJAN(富捷); AddInBom: yes; ModelId: efdecb7dae4442949d28eecaf748420f0819f05c4eef4c71ace90d822a990e87; ModelName: R0402_L1.0-W0.5-H0.4; ModelTransform: 39.37,19.685,0,0,0,0,0,0,0; Tolerance: ±5%; Power(Watts): 62.5mW; Voltage-Supply(Max): 50V
R3 R26-R30 = FRC0402J102 TS: Type:Thick Film Resistor Resistance:1kΩ Tolerance:±5% Tolerance:±5% Power(Watts):62.5mW Voltage-Supply(Max):50V Temperature Coefficient:±100ppm/℃ Temperature Coefficient:±100ppm/℃ Operating Temperature:-55℃~+155℃ Operating Temperature:-55℃~+155℃; Manufacturer: FOJAN(富捷); AddInBom: yes; ModelId: efdecb7dae4442949d28eecaf748420f0819f05c4eef4c71ace90d822a990e87; ModelName: R0402_L1.0-W0.5-H0.4; ModelTransform: 39.37,19.685,0,0,0,0,0,0,0; Tolerance: ±5%; Power(Watts): 62.5mW; Voltage-Supply(Max): 50V
R4 R40 = FRC0402F1201TS: Type:Thick Film Resistor Resistance:1.2kΩ Tolerance:±1% Tolerance:±1% Power(Watts):62.5mW Voltage-Supply(Max):50V Temperature Coefficient:±100ppm/℃ Temperature Coefficient:±100ppm/℃ Operating Temperature:-55℃~+155℃ Operating Temperature:-55℃~+155℃; Manufacturer: FOJAN(富捷); AddInBom: yes; ModelId: efdecb7dae4442949d28eecaf748420f0819f05c4eef4c71ace90d822a990e87; ModelName: R0402_L1.0-W0.5-H0.4; ModelTransform: 39.37,19.685,0,0,0,0,0,0,0; Tolerance: ±1%; Power(Watts): 62.5mW; Voltage-Supply(Max): 50V
R5 R17-R25 = FRC0402F1002TS: Type:Thick Film Resistor Resistance:10kΩ Tolerance:±1% Tolerance:±1% Power(Watts):62.5mW Voltage-Supply(Max):50V Temperature Coefficient:±100ppm/℃ Temperature Coefficient:±100ppm/℃ Operating Temperature:-55℃~+155℃ Operating Temperature:-55℃~+155℃; Manufacturer: FOJAN(富捷); AddInBom: yes; ModelId: efdecb7dae4442949d28eecaf748420f0819f05c4eef4c71ace90d822a990e87; ModelName: R0402_L1.0-W0.5-H0.4; ModelTransform: 39.37,19.685,0,0,0,0,0,0,0; Tolerance: ±1%; Power(Watts): 62.5mW; Voltage-Supply(Max): 50V
R6 R42 = FRC0402F2002TS: Type:Thick Film Resistor Resistance:20kΩ Tolerance:±1% Tolerance:±1% Power(Watts):62.5mW Voltage-Supply(Max):50V Temperature Coefficient:±100ppm/℃ Temperature Coefficient:±100ppm/℃ Operating Temperature:-55℃~+155℃ Operating Temperature:-55℃~+155℃; Manufacturer: FOJAN(富捷); AddInBom: yes; ModelId: efdecb7dae4442949d28eecaf748420f0819f05c4eef4c71ace90d822a990e87; ModelName: R0402_L1.0-W0.5-H0.4; ModelTransform: 39.37,19.685,0,0,0,0,0,0,0; Tolerance: ±1%; Power(Watts): 62.5mW; Voltage-Supply(Max): 50V
R7 R43 = FRC0402F6202TS: Type:Thick Film Resistor Resistance:62kΩ Tolerance:±1% Tolerance:±1% Power(Watts):62.5mW Voltage-Supply(Max):50V Temperature Coefficient:±100ppm/℃ Temperature Coefficient:±100ppm/℃ Operating Temperature:-55℃~+155℃ Operating Temperature:-55℃~+155℃; Manufacturer: FOJAN(富捷); AddInBom: yes; ModelId: efdecb7dae4442949d28eecaf748420f0819f05c4eef4c71ace90d822a990e87; ModelName: R0402_L1.0-W0.5-H0.4; ModelTransform: 39.37,19.685,0,0,0,0,0,0,0; Tolerance: ±1%; Power(Watts): 62.5mW; Voltage-Supply(Max): 50V
R8 R31-R33 = FRC0402J104 TS: Type:Thick Film Resistor Resistance:100kΩ Tolerance:±5% Tolerance:±5% Power(Watts):62.5mW Voltage-Supply(Max):50V Temperature Coefficient:±100ppm/℃ Temperature Coefficient:±100ppm/℃ Operating Temperature:-55℃~+155℃ Operating Temperature:-55℃~+155℃; Manufacturer: FOJAN(富捷); AddInBom: yes; ModelId: efdecb7dae4442949d28eecaf748420f0819f05c4eef4c71ace90d822a990e87; ModelName: R0402_L1.0-W0.5-H0.4; ModelTransform: 39.37,19.685,0,0,0,0,0,0,0; Tolerance: ±5%; Power(Watts): 62.5mW; Voltage-Supply(Max): 50V
R9 = FRC0402J331 TS: Type:Thick Film Resistor Resistance:330Ω Tolerance:±5% Tolerance:±5% Power(Watts):62.5mW Voltage-Supply(Max):50V Temperature Coefficient:±100ppm/℃ Temperature Coefficient:±100ppm/℃ Operating Temperature:-55℃~+155℃ Operating Temperature:-55℃~+155℃; Manufacturer: FOJAN(富捷); AddInBom: yes; ModelId: efdecb7dae4442949d28eecaf748420f0819f05c4eef4c71ace90d822a990e87; ModelName: R0402_L1.0-W0.5-H0.4; ModelTransform: 39.37,19.685,0,0,0,0,0,0,0; Tolerance: ±5%; Power(Watts): 62.5mW; Voltage-Supply(Max): 50V
R10-R16 R34 R35 = FRC0603F1000TS: Type:Thick Film Resistor Resistance:100Ω Tolerance:±1% Tolerance:±1% Power(Watts):100mW Voltage-Supply(Max):75V Temperature Coefficient:±100ppm/℃ Temperature Coefficient:±100ppm/℃ Operating Temperature:-55℃~+155℃ Operating Temperature:-55℃~+155℃; Manufacturer: FOJAN(富捷); AddInBom: yes; ModelId: 112863783b5b41f1b5254f87eedc79320819f05c4eef4c71ace90d822a990e87; ModelTransform: 31.8897,63.7794,0,90,0,0,0,0,0; Tolerance: ±1%; Power(Watts): 100mW; Voltage-Supply(Max): 75V
R36-R39 = FRC0402J472 TS: Type:Thick Film Resistor Resistance:4.7kΩ Tolerance:±5% Tolerance:±5% Power(Watts):62.5mW Voltage-Supply(Max):50V Temperature Coefficient:±100ppm/℃ Temperature Coefficient:±100ppm/℃ Operating Temperature:-55℃~+155℃ Operating Temperature:-55℃~+155℃; Manufacturer: FOJAN(富捷); AddInBom: yes; ModelId: efdecb7dae4442949d28eecaf748420f0819f05c4eef4c71ace90d822a990e87; ModelName: R0402_L1.0-W0.5-H0.4; ModelTransform: 39.37,19.685,0,0,0,0,0,0,0; Tolerance: ±5%; Power(Watts): 62.5mW; Voltage-Supply(Max): 50V
R41 = RTT03R010FTP: Type:Thick Film Resistor Resistance:10mΩ Tolerance:±1% Tolerance:±1% Power(Watts):100mW Temperature Coefficient:±1500ppm/℃ Temperature Coefficient:±1500ppm/℃ Operating Temperature:-55℃~+155℃ Operating Temperature:-55℃~+155℃; Manufacturer: RALEC(旺诠); AddInBom: yes; ModelId: 112863783b5b41f1b5254f87eedc79320819f05c4eef4c71ace90d822a990e87; ModelTransform: 31.8897,63.7794,0,90,0,0,0,0,0; Tolerance: ±1%; Power(Watts): 100mW
U1 = RP2350B_C42415655: Number of I/O:48 Features:Independent watchdog (IWDG)；Power-on reset (POR)；True random number generator (TRNG)；Watchdog reset；Built-in general-purpose timer；Hardware ECC check；External pin reset (NRST)；Integrated LDO; Manufacturer: Raspberry Pi(树莓派); Add into BOM: yes; ModelId: 9f007f8a42644ad5aa4c6524189812eb0819f05c4eef4c71ace90d822a990e87; ModelTransform: 394.487,394.487,0,0,0,0,0,0,0; Number of I/O: 48
U2 = CH224K: Type:Power Receiver Controller Protocol:PD 3.0 Number of Channels:- Output Power:100W Output Voltage:5V；20V；15V；12V；9V Voltage - Supply:4V~30V Voltage - Supply:4V~30V Operating Temperature:-40℃~+90℃ Operating Temperature:-40℃~+90℃ Features:Thermal Protect; Manufacturer: WCH(南京沁恒); Add into BOM: yes; ModelId: caddd54494d446ce85a816aa480d5ff10819f05c4eef4c71ace90d822a990e87; ModelTransform: 192.913,236.22,0,0,0,0,0,0,0; Protocol: PD 3.0; Output Power: 100W; Voltage - Supply: 4V~30V
U3 = BQ25798RQMR: The Chip Type:Charging IC Voltage - Supply:3.6V~24V Voltage - Supply:3.6V~24V Charge Current - Max:5A Type of Battery:Lithium Battery Number of Cells:1~4 Number of Cells:1~4 Operating Temperature:-40℃~+85℃ Operating Temperature:-40℃~+85℃ Battery Temperatu; Manufacturer: TI(德州仪器); Add into BOM: yes; ModelId: 359ccb1411cf4750b283dd43433afa970819f05c4eef4c71ace90d822a990e87; ModelTransform: 158.267,158.267,0,0,0,0,0,-0.197,0; Charge Current - Max: 5A; Number of Cells: 1~4; Battery Temperature Detection: Support; Supply Current (Iq): 17uA; Interface: I2C
U4 = TPS563201DDCR: Function:Step-down type Voltage - Supply:4.5V~17V Voltage - Supply:4.5V~17V Output Voltage:768mV~7V Output Voltage:768mV~7V Output Current:3A Frequency - Switching:580kHz Frequency - Switching:580kHz Operating Temperature:-40℃~+125℃@(TJ) Operating Tempera; Manufacturer: TI(德州仪器); Add into BOM: yes; ModelId: 1370be37a17e44418ae52e2b4cc1f5e50819f05c4eef4c71ace90d822a990e87; ModelName: SOT-23-6_L2.9-W1.6-H1.5-LS2.8-P0.95; ModelTransform: 110.73671,114.173,0,180,0,0,0.001,-0.003,0; Output Current: 3A; Frequency - Switching: 580kHz; Number of Outputs: 1; Topology: Buck; Quiescent Current: 380uA; Switch tube (built-in/external): Built-in; Output Type: Adjustable
U5 = TPS54202DDCR: Function:Step-down type Voltage - Supply:4.5V~28V Voltage - Supply:4.5V~28V Output Voltage:- Output Voltage:- Output Current:2A Frequency - Switching:500kHz Frequency - Switching:500kHz Operating Temperature:-40℃~+125℃@(TJ) Operating Temperature:-40℃~+125; Manufacturer: TI(德州仪器); Add into BOM: yes; ModelId: 1370be37a17e44418ae52e2b4cc1f5e50819f05c4eef4c71ace90d822a990e87; ModelName: SOT-23-6_L2.9-W1.6-H1.5-LS2.8-P0.95; ModelTransform: 110.236,113.364,0,90,0,0,0.0005,0.0005,0; Output Current: 2A; Frequency - Switching: 500kHz; Number of Outputs: 1; Topology: Buck; Quiescent Current: 45uA; Switch tube (built-in/external): Built-in; Output Type: Adjustable
U6 = W25Q32JVSSIQ_C82344: Interface:SPI Memory Size:32Mbit Clock Frequency:133MHz Voltage - Supply:2.7V~3.6V Voltage - Supply:2.7V~3.6V Standby Supply Current:10uA Program / Erase Cycles:100,000 cycles Write Cycle Time (tWC):- Page Programming Time (Tpp):3ms Block Erase Time(tBE):; Manufacturer: Winbond(华邦); Add into BOM: yes; ModelId: 7b3104f4a302484e875593c5ba7bd3db0819f05c4eef4c71ace90d822a990e87; ModelName: SOIC-8_L5.3-W5.3-H1.9-LS7.9-P1.27; ModelTransform: 208.661,311.25654,0,0,0,0,-0.0005,0.0005,0; Interface: SPI; Memory Size: 32Mbit; Clock Frequency: 133MHz; Standby Supply Current: 10uA; Page Programming Time (Tpp): 3ms; Block Erase Time(tBE): 120ms@(32KB); Data Retention - TDR (Year): 20 Years
U7 = APS6404L-3SQR-ZR: Manufacturer: Apmemory; Add into BOM: yes; ModelId: 2b35e1c3dcc44b77887d4f445b51370a0819f05c4eef4c71ace90d822a990e87; ModelName: USON-8_L2-W3-H0.6X0.5P; ModelTransform: 79.527,118.8974,0,0,0,0,-0.313,-1.1,0
U8 U9 = INA226AIDGSR: Number of Channels:- Vcm - Common Mode Voltage:0V~36V Vcm - Common Mode Voltage:0V~36V Gain:- Bandwidth:- Ib - Input Bias Current:100pA Vos - Input Offset Voltage:2.5uV Operating Temperature:-40℃~+125℃ Operating Temperature:-40℃~+125℃ Differential Voltage; Manufacturer: TI(德州仪器); Add into BOM: yes; ModelId: 875cf331c88d40d1aea94374997f39b10819f05c4eef4c71ace90d822a990e87; ModelName: MSOP-10_L3.0-W3.0-H1.1-LS5.0-P0.50; ModelTransform: 118.11,196.85,0,0,0,0,0,0,0; Vcm - Common Mode Voltage: 0V~36V; Ib - Input Bias Current: 100pA; Vos - Input Offset Voltage: 2.5uV; Differential Voltage: ±40V; Single Supply: 2.7V~5.5V; Quiescent Current: 330uA; Input Offset Voltage Drift(Vos TC): 0.1uV/℃; Common Mode Rejection Ratio (CMRR): 140dB
U10 = LPS22HBTR: Pressure range:26Kpa~1.26bar Pressure range:26Kpa~1.26bar Voltage - Supply:1.7V~3.6V Voltage - Supply:1.7V~3.6V Standby Current:1uA Interface:SPI；I2C Module:No Absolute Accuracy:0.1hpa Relative Accuracy:0.1hpa Features:On-chip temperature compensation；Int; Manufacturer: ST(意法半导体); Add into BOM: yes; ModelId: 02ad9adc3b5149f0a499482c2afb62890819f05c4eef4c71ace90d822a990e87; ModelName: HLGA-10L_L2.0-W2.0-H0.8-P0.5-LPS22HBTR; ModelTransform: 78.74,78.74,0,0,0,0,0,0.195,0; Standby Current: 1uA; Module: No; Absolute Accuracy: 0.1hpa
U11 = BME680: Pressure range:30Kpa~1.1bar Pressure range:30Kpa~1.1bar Voltage - Supply:1.71V~3.6V Voltage - Supply:1.71V~3.6V Standby Current:150nA Interface:SPI；I2C Module:- Absolute Accuracy:0.6hpa Relative Accuracy:0.12hpa Features:Standby mode；Integrated ADC and di; Manufacturer: Bosch(博世); Add into BOM: yes; ModelId: b8c5a93640fd43cf889b444887718f200819f05c4eef4c71ace90d822a990e87; ModelName: LGA-8_L3.0-W3.0-H0.9-P0.80-TR; ModelTransform: 118.11,118.11,0,0,0,0,0,0,0; Standby Current: 150nA; Absolute Accuracy: 0.6hpa; Temperature Coefficient of Offset(TCO): 1.3pa/K
U12 = MTP20-B6CO2: Type:Carbon dioxide Operating Temperature:-30℃~+100℃ Operating Temperature:-30℃~+100℃; Manufacturer: MFrontier(美思先端); Add into BOM: yes
U13 = LIS3MDLTR: Magnetic Sensing Range(X,Y):±1.2mT；±1.6mT；±4Gs；±8Gs Magnetic Sensing Range(X,Y):±1.2mT；±1.6mT；±4Gs；±8Gs Magnetic Sensing Range(Z):±4Gs；±1.2mT；±8Gs；±1.6mT Magnetic Sensing Range(Z):±4Gs；±1.2mT；±8Gs；±1.6mT Output bit:16bit Interface Type:SPI；I2C Voltage - S; Manufacturer: ST(意法半导体); Add into BOM: yes; ModelId: 08d0e00f89c34818888f739e33f114130819f05c4eef4c71ace90d822a990e87; ModelName: LGA-12_L2.0-W2.0-H1.0-P0.50; ModelTransform: 78.74,78.74,0,90,0,0,0,0.001,0; Output bit: 16bit; Voltage - Supply: 1.9V~3.6V; Current - Supply: 270uA；1uA；40uA
U14 = LSM9DS1TR: Accelerometer Sensing Axis:X,Y,Z Acceleration Measurement Range (MAX):±16g Acceleration Measurement Range (MAX):±16g Gyroscope Sensing Axis:X,Y,Z Gyroscope Measurement Range (MAX):±2000dps Gyroscope Measurement Range (MAX):±2000dps Sensor Type:IMU (accele; Manufacturer: ST(意法半导体); Add into BOM: yes; ModelId: 06729e712fbf436e90dfd5c95b7315ee0819f05c4eef4c71ace90d822a990e87; ModelTransform: 137.795,118.11,0,0,0,0,0,0,0; Accelerometer Sensing Axis: X,Y,Z; Acceleration Measurement Range (MAX): ±16g; Sensor Type: IMU (accelerometer + gyroscope); Output Bits: 16bit; Interface: I2C；SPI; Voltage - Supply: 1.9V~3.6V
U15 = BNO055: Accelerometer Sensing Axis:X,Y,Z Acceleration Measurement Range (MAX):±16g Acceleration Measurement Range (MAX):±16g Gyroscope Sensing Axis:X,Y,Z Gyroscope Measurement Range (MAX):±2000dps Gyroscope Measurement Range (MAX):±2000dps Sensor Type:IMU (accele; Manufacturer: Bosch(博世); Add into BOM: yes; ModelId: 2256a7a8c01e4b8c876389a77bde68f70819f05c4eef4c71ace90d822a990e87; ModelName: LGA-28_L5.2-W3.8-H1.2-P0.50-BL; ModelTransform: 204.724,149.606,0,90,0,0,-0.004,0.004,0; Accelerometer Sensing Axis: X,Y,Z; Acceleration Measurement Range (MAX): ±16g; Sensor Type: IMU (accelerometer + gyroscope); Output Bits: 14bit；16bit; Interface: UART；I2C; Voltage - Supply: 2.4V~3.6V; Standby Current: 40uA
U16 U22 = EVQ-Q2P02W: Circuit:SPST Actuator Style:Round Button Operating Force:1.6N Mounting Type:Surface Mount,Vertical Length:6.5mm Width:6mm Switch Height:2.5mm Contact Current:20mA Voltage Rating:15V With Lamp:- IP Rating:- Termination Style:J-Lead Life:1,000,000 cycles Op; Manufacturer: PANASONIC(松下); Add into BOM: yes; ModelId: fe986412e056403e95cd55841a82b76e0819f05c4eef4c71ace90d822a990e87; ModelTransform: 260.751,240.337,0,0,0,0,-0.001,0,0; Circuit: SPST; Operating Force: 1.6N; Switch Height: 2.5mm; Contact Current: 20mA; Voltage Rating: 15V
U17 = IM63D135AXTMA1: Direction:Omnidirectional Voltage - Supply:1.8V Voltage - Supply:1.8V Current Consumption:1.1mA~1.4mA Current Consumption:1.1mA~1.4mA S/N Ratio:63.5dB Sensitivity:-41dB Sensitivity:-41dB Length:3.5mm Width:2.65mm Height:0.98mm Operating Temperature:-40℃~+; Manufacturer: Infineon(英飞凌); Add into BOM: yes; ModelId: d3258170ac2d45d5985ecf8dc254410c0819f05c4eef4c71ace90d822a990e87; ModelTransform: 104.3305,137.795,0,0,0,0,0,2.402,0; Voltage - Supply: 1.8V; S/N Ratio: 63.5dB; Sensitivity: -41dB
U18 = ADAU1450WBCPZ-RL: Operating Temperature Range:-40℃~+105℃ Operating Temperature Range:-40℃~+105℃; Manufacturer: ADI(亚德诺); Add into BOM: yes; ModelId: e0591baa79fb4cafa64304a2951a30980819f05c4eef4c71ace90d822a990e87; ModelName: LFCSP-72_L10.0-W9.8-H1.0-P0.50; ModelTransform: 394.487,386.6134,0,0,0,0,-0.591,0.392,0
U19 U23-U30 = B3B-XH-A(LF)(SN): Pins Structure:1x3P Pitch:2.5mm Mounting Type:Through Hole Reference Series:XH Number of Pins:3P Number of Rows:1 Number of PINs Per Row:3 Row Spacing:- Current Rating:3A Contact Material:Brass Contact Plating:Tin Operating Temperature:-25℃~+85℃ Operating; Manufacturer: JST; Add into BOM: yes; ModelId: 5bef03a823d44d6d8bbe2419212192340819f05c4eef4c71ace90d822a990e87; ModelTransform: 393.7,226.3775,0,0,0,0,-0.005,-18.465,-125.984; Pins Structure: 1x3P; Pitch: 2.5mm; Reference Series: XH; Number of PINs Per Row: 3; Current Rating: 3A; Voltage Rating: 250V; Plastic Material: PA66; Flame Retardant Rating: UL94V-0; Supplementary Features: K Pin; Z-Height of the Board: 7mm; X-Length of Bottom Edge on Board (Spacing Line): 9.9mm; Y-Width of Bottom Edge on Board: 5.75mm
U20 U31 U32 = 2.54-1*4: Pin Structure:1x4P Pitch:2.54mm Circluar Pins/Square Pins:Pin Header Mounting Type:Through Hole Number of Rows:1 Number of Pins:4P Current Rating:2.5A Length of Mating Pin:6mm Insulation Height:2.54mm Length of End Connection Pin:3mm Contact Material:Bras; Manufacturer: ZHOURI(洲日); Add into BOM: yes; ModelId: e2e03939c192453cba872779c0cb63900819f05c4eef4c71ace90d822a990e87; ModelTransform: 400.039,100,0,0,0,0,0,0,-118.11; Pin Structure: 1x4P; Pitch: 2.54mm; Current Rating: 2.5A
U21 = HX PM1.27-2x3P ZC: Holes Structure:2x3P Pitch:1.27mm Row Spacing:1.27mm Circular Hole / Square Hole:Square Hole Mounting Type:Through Hole Number of Rows:2 Number of Positions:6P Current Rating:1A Voltage Rating (Max):500V Holes Direction:Top Insulation Height:4.3mm Contact; Manufacturer: hanxia(韩下); Add into BOM: yes; Holes Structure: 2x3P; Pitch: 1.27mm; Number of Positions: 6P; Current Rating: 1A; Voltage Rating (Max): 500V; Holes Direction: Top; PIN Length: 2.4mm
USBC1 = TYPE-C-31-M-12: Connector Type:Type-C Protocol Standard:- Gender:Female Mounting Type:Surface Mount, Right Angle Number of Contacts:16P Number of Ports:1 Current Rating-Power:5A Voltage Rating:20V Connect-Disconnect Life:10,000 cycles Length:7.35mm Operating Temperature:; Manufacturer: 韩国韩荣; Add into BOM: yes; ModelId: 8421221a464047838322348b3a9debc30819f05c4eef4c71ace90d822a990e87; ModelTransform: 351.9678,311.023,0,180,0,0,0,-43.307,-33.465; Connector Type: Type-C; Gender: Female; Number of Contacts: 16P; Number of Ports: 1; Current Rating-Power: 5A; Voltage Rating: 20V
X1 = X49SM12MSD2SC: Type:Crystal Oscillator Frequency:12MHz Normal temperature Frequency Tolerance:±20ppm Normal temperature Frequency Tolerance:±20ppm Load Capacitance:20pF Frequency Stability:±30ppm Frequency Stability:±30ppm Operating Temperature:-20℃~+70℃ Operating Tempe; Manufacturer: YXC(扬兴晶振); Add into BOM: yes; ModelId: c2ec6472aa1a474698dd1da780b3c79b0819f05c4eef4c71ace90d822a990e87; ModelName: HC-49S_L11.4-W1.8-H3.0-LS12.7; ModelTransform: 499.999,188.976,0,0,0,0,0,0,0; Normal temperature Frequency Tolerance: ±20ppm; Load Capacitance: 20pF; Frequency Stability: ±30ppm
X2 = NX3225GA-12.288MHz-STD-CRG-2: Type:- Frequency:- Load Capacitance:- Operating Temperature:- Operating Temperature:-; Manufacturer: NDK; Add into BOM: yes; ModelId: a2b47bc5d32f4dfd996128e047b549a00819f05c4eef4c71ace90d822a990e87; ModelTransform: 125.984,98.425,0,0,0,0,0,0,0
ZD1 = MMSZ5245B_C2126: Diode Configuration:1 Independent Zener Voltage(Nom):15V Reverse Leakage Current (Ir):100nA Zener Voltage(Range):14.25V~15.75V Zener Voltage(Range):14.25V~15.75V Pd - Power Dissipation:350mW Impedance(Zzt):16Ω Impedance(Zzk):600Ω Operating Junction Temper; Manufacturer: CJ(江苏长电/长晶); Add into BOM: yes; ModelId: 560a7cf99d0e44cb9af362aaf5d7923d0819f05c4eef4c71ace90d822a990e87; ModelTransform: 144.8816,62.992,0,0,0,0,0,0,0; Zener Voltage(Nom): 15V; Reverse Leakage Current (Ir): 100nA; Pd - Power Dissipation: 350mW; Impedance(Zzt): 16Ω; Impedance(Zzk): 600Ω; Operating Junction Temperature Range: -65℃~+150℃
